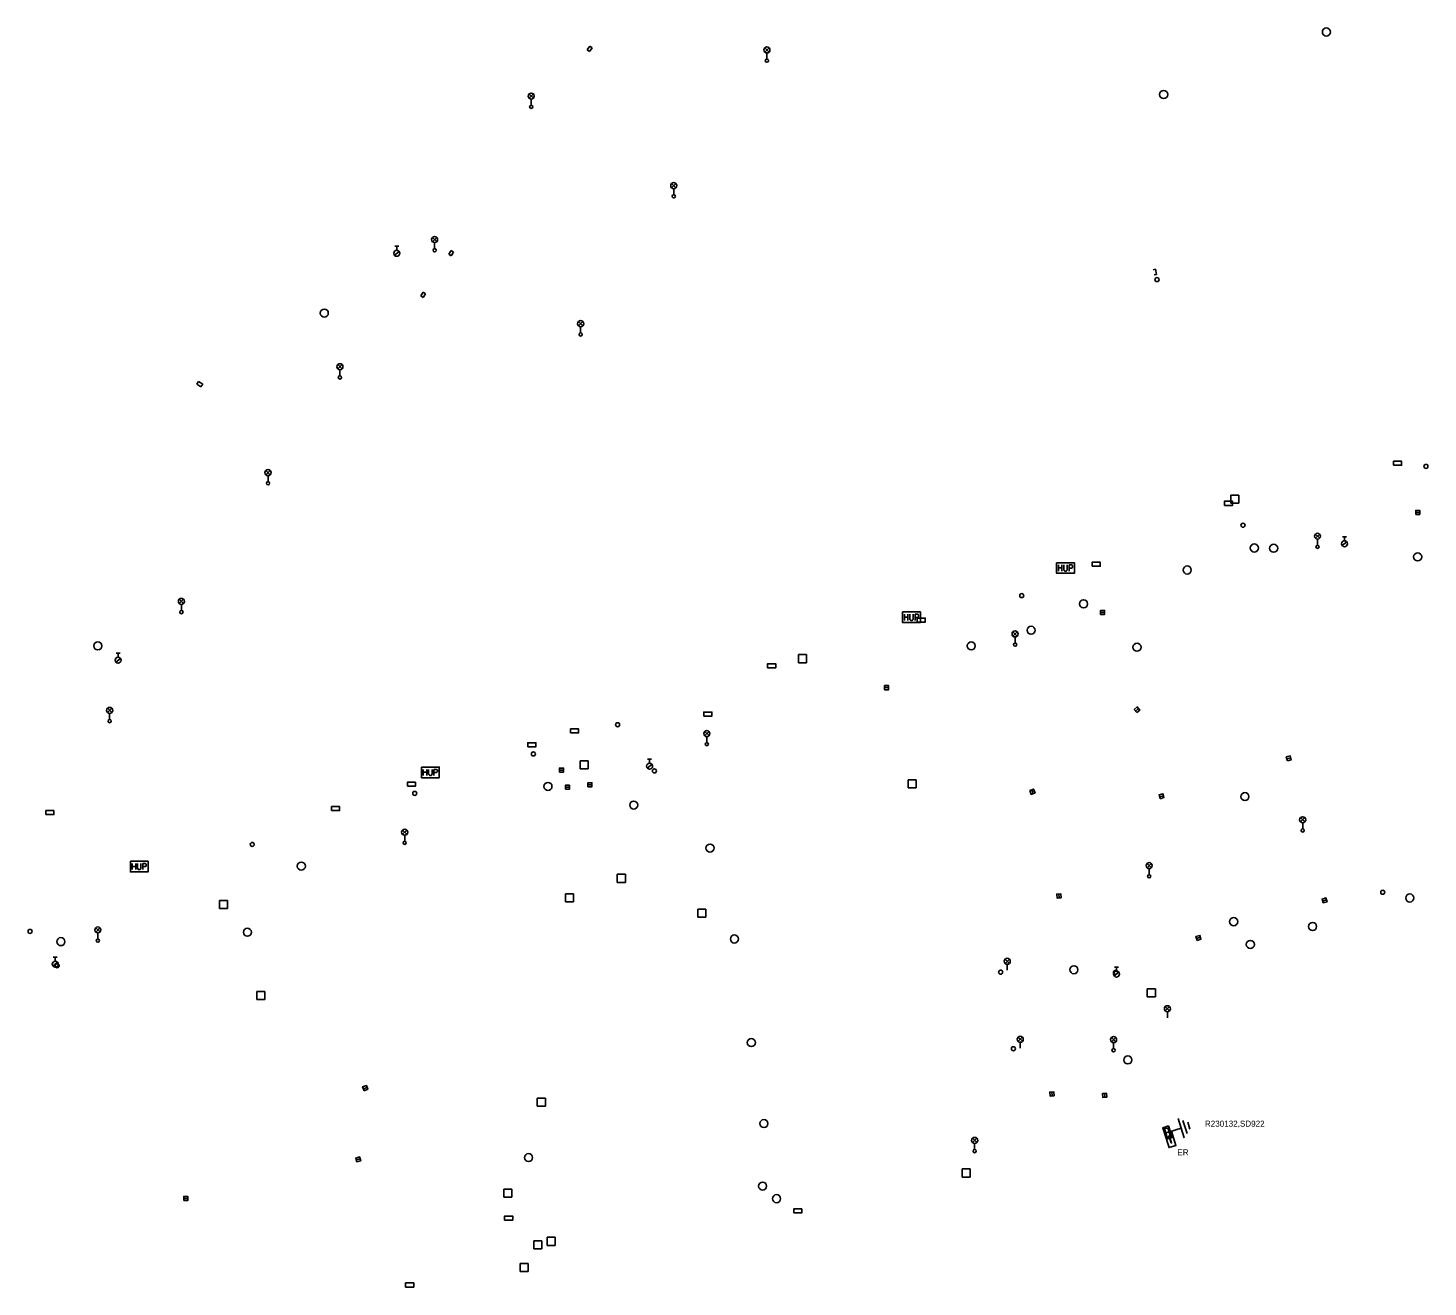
# Model space of a CAD drawing. Extents: x -584388 to -581645, y -1210859 to -1208922.
# Drawn here: x -583193 to -583019.2, y -1210722.4 to -1210566.1 of the extents above; entities that cross this region are included whole.
import ezdxf

# ---------------------------------------------------------------- set-up
doc = ezdxf.new("R2010")
doc.units = 0
for name, color, linetype in [('CIZÍ_NADZEM', 7, 'Continuous'), ('CIZÍ_PODZEM', 7, 'Continuous'), ('ELE_EON', 7, 'Continuous'), ('ELE_EON_POPIS', 7, 'Continuous')]:
    doc.layers.add(name, color=color, linetype=linetype)

msp = doc.modelspace()

# ---------------------------------------------------------------- linework, layer by layer
at = {"layer": 'CIZÍ_NADZEM'}
for p, q in [((-583101.55, -1210569.09), (-583101.03, -1210568.56)), ((-583101.02, -1210569.08), (-583101.55, -1210568.56)), ((-583101.29, -1210569.2), (-583101.29, -1210569.95)), ((-583130.82, -1210574.82), (-583130.3, -1210574.29)), ((-583130.29, -1210574.81), (-583130.82, -1210574.29)), ((-583130.56, -1210574.93), (-583130.56, -1210575.68)), ((-583113.12, -1210585.93), (-583112.6, -1210585.4)), ((-583112.59, -1210585.93), (-583113.12, -1210585.4)), ((-583112.86, -1210586.04), (-583112.86, -1210586.79)), ((-583142.81, -1210592.63), (-583142.29, -1210592.1)), ((-583142.28, -1210592.62), (-583142.81, -1210592.1)), ((-583147.54, -1210594.3), (-583146.95, -1210593.84)), ((-583147.5, -1210593.2), (-583147, -1210593.2)), ((-583147.25, -1210593.7), (-583147.25, -1210593.2)), ((-583142.55, -1210592.74), (-583142.55, -1210593.49)), ((-583124.68, -1210603.08), (-583124.16, -1210602.55)), ((-583124.15, -1210603.07), (-583124.68, -1210602.55)), ((-583124.42, -1210603.19), (-583124.42, -1210603.94)), ((-583154.57, -1210608.42), (-583154.05, -1210607.89)), ((-583154.04, -1210608.42), (-583154.57, -1210607.89)), ((-583154.31, -1210608.53), (-583154.31, -1210609.28)), ((-583163.5, -1210621.56), (-583162.98, -1210621.03)), ((-583162.97, -1210621.56), (-583163.5, -1210621.03)), ((-583163.24, -1210621.67), (-583163.24, -1210622.42)), ((-583042.71, -1210624.1), (-583043.71, -1210624.1)), ((-583043.71, -1210624.1), (-583043.71, -1210625.1)), ((-583043.71, -1210625.1), (-583042.71, -1210625.1)), ((-583042.71, -1210625.1), (-583042.71, -1210624.1)), ((-583020.74, -1210626.25), (-583020.24, -1210626.25)), ((-583033.19, -1210629.46), (-583032.67, -1210628.93)), ((-583032.66, -1210629.46), (-583033.19, -1210628.93)), ((-583032.93, -1210629.57), (-583032.93, -1210630.32)), ((-583029.87, -1210630.37), (-583029.28, -1210629.91)), ((-583029.83, -1210629.27), (-583029.33, -1210629.27)), ((-583029.58, -1210629.77), (-583029.58, -1210629.27)), ((-583174.25, -1210637.57), (-583173.73, -1210637.04)), ((-583173.72, -1210637.56), (-583174.25, -1210637.04)), ((-583173.99, -1210637.68), (-583173.99, -1210638.43)), ((-583059.86, -1210638.66), (-583059.36, -1210638.66)), ((-583070.74, -1210641.61), (-583070.22, -1210641.08)), ((-583070.21, -1210641.6), (-583070.74, -1210641.08)), ((-583070.48, -1210641.72), (-583070.48, -1210642.47)), ((-583182.1, -1210643.73), (-583181.6, -1210643.73)), ((-583181.85, -1210644.23), (-583181.85, -1210643.73)), ((-583096.39, -1210643.91), (-583097.39, -1210643.91)), ((-583097.39, -1210643.91), (-583097.39, -1210644.91)), ((-583096.39, -1210644.91), (-583096.39, -1210643.91)), ((-583182.14, -1210644.83), (-583181.55, -1210644.37)), ((-583097.39, -1210644.91), (-583096.39, -1210644.91)), ((-583086.69, -1210648.01), (-583086.19, -1210648.01)), ((-583183.16, -1210651.1), (-583182.64, -1210650.57)), ((-583182.63, -1210651.09), (-583183.16, -1210650.57)), ((-583055.53, -1210650.92), (-583055.15, -1210650.6)), ((-583182.9, -1210651.21), (-583182.9, -1210651.96)), ((-583109.01, -1210653.97), (-583108.49, -1210653.44)), ((-583108.48, -1210653.97), (-583109.01, -1210653.44)), ((-583108.75, -1210654.08), (-583108.75, -1210654.83)), ((-583123.5, -1210657.1), (-583124.5, -1210657.1)), ((-583124.5, -1210657.1), (-583124.5, -1210658.1)), ((-583124.5, -1210658.1), (-583123.5, -1210658.1)), ((-583123.5, -1210658.1), (-583123.5, -1210657.1)), ((-583116.15, -1210657.99), (-583115.56, -1210657.53)), ((-583116.11, -1210656.89), (-583115.61, -1210656.89)), ((-583115.86, -1210657.39), (-583115.86, -1210656.89)), ((-583036.73, -1210656.86), (-583036.25, -1210656.72)), ((-583127.05, -1210658.24), (-583126.55, -1210658.24)), ((-583082.76, -1210659.47), (-583083.76, -1210659.47)), ((-583083.76, -1210659.47), (-583083.76, -1210660.47)), ((-583082.76, -1210660.47), (-583082.76, -1210659.47)), ((-583126.32, -1210660.38), (-583125.82, -1210660.38)), ((-583123.52, -1210660.07), (-583123.02, -1210660.07)), ((-583083.76, -1210660.47), (-583082.76, -1210660.47)), ((-583068.42, -1210660.7), (-583068.24, -1210661.16)), ((-583052.54, -1210661.57), (-583052.06, -1210661.43)), ((-583035.03, -1210664.68), (-583034.51, -1210664.15)), ((-583034.5, -1210664.68), (-583035.03, -1210664.15)), ((-583034.77, -1210664.79), (-583034.77, -1210665.54)), ((-583146.53, -1210666.22), (-583146.01, -1210665.69)), ((-583146, -1210666.22), (-583146.53, -1210665.69)), ((-583146.27, -1210666.33), (-583146.27, -1210667.08)), ((-583054.09, -1210670.38), (-583053.57, -1210669.85)), ((-583053.56, -1210670.38), (-583054.09, -1210669.85)), ((-583118.87, -1210671.19), (-583119.87, -1210671.19)), ((-583119.87, -1210671.19), (-583119.87, -1210672.19)), ((-583118.87, -1210672.19), (-583118.87, -1210671.19)), ((-583053.83, -1210670.49), (-583053.83, -1210671.24)), ((-583125.29, -1210673.62), (-583126.29, -1210673.62)), ((-583126.29, -1210673.62), (-583126.29, -1210674.62)), ((-583125.29, -1210674.62), (-583125.29, -1210673.62)), ((-583119.87, -1210672.19), (-583118.87, -1210672.19)), ((-583065.02, -1210674.13), (-583065.06, -1210673.63)), ((-583168.28, -1210674.44), (-583169.28, -1210674.44)), ((-583169.28, -1210674.44), (-583169.28, -1210675.44)), ((-583169.28, -1210675.44), (-583168.28, -1210675.44)), ((-583168.28, -1210675.44), (-583168.28, -1210674.44)), ((-583126.29, -1210674.62), (-583125.29, -1210674.62)), ((-583108.89, -1210675.5), (-583109.89, -1210675.5)), ((-583109.89, -1210675.5), (-583109.89, -1210676.5)), ((-583108.89, -1210676.5), (-583108.89, -1210675.5)), ((-583032.29, -1210674.51), (-583031.81, -1210674.37)), ((-583109.89, -1210676.5), (-583108.89, -1210676.5)), ((-583184.63, -1210678.36), (-583184.11, -1210677.83)), ((-583184.1, -1210678.35), (-583184.63, -1210677.83)), ((-583184.37, -1210678.47), (-583184.37, -1210679.22)), ((-583047.95, -1210679.15), (-583047.47, -1210679.01)), ((-583189.95, -1210682.58), (-583189.36, -1210682.12)), ((-583189.91, -1210681.48), (-583189.41, -1210681.48)), ((-583189.66, -1210681.98), (-583189.66, -1210681.48)), ((-583071.71, -1210682.25), (-583071.19, -1210681.72)), ((-583071.18, -1210682.25), (-583071.71, -1210681.72)), ((-583071.45, -1210683.11), (-583071.45, -1210682.36)), ((-583058.18, -1210683.81), (-583057.59, -1210683.35)), ((-583058.14, -1210682.71), (-583057.64, -1210682.71)), ((-583057.89, -1210683.21), (-583057.89, -1210682.71)), ((-583163.63, -1210685.73), (-583164.63, -1210685.73)), ((-583164.63, -1210685.73), (-583164.63, -1210686.73)), ((-583163.63, -1210686.73), (-583163.63, -1210685.73)), ((-583053.06, -1210685.41), (-583054.06, -1210685.41)), ((-583054.06, -1210685.41), (-583054.06, -1210686.41)), ((-583053.06, -1210686.41), (-583053.06, -1210685.41)), ((-583164.63, -1210686.73), (-583163.63, -1210686.73)), ((-583054.06, -1210686.41), (-583053.06, -1210686.41)), ((-583051.83, -1210688.14), (-583051.31, -1210687.61)), ((-583051.3, -1210688.14), (-583051.83, -1210687.61)), ((-583051.57, -1210689), (-583051.57, -1210688.25)), ((-583070.1, -1210691.93), (-583069.58, -1210691.4)), ((-583069.57, -1210691.93), (-583070.1, -1210691.4)), ((-583069.84, -1210692.79), (-583069.84, -1210692.04)), ((-583058.51, -1210691.98), (-583057.99, -1210691.45)), ((-583057.98, -1210691.98), (-583058.51, -1210691.45)), ((-583058.25, -1210692.09), (-583058.25, -1210692.84)), ((-583151.4, -1210697.83), (-583150.94, -1210697.65)), ((-583128.8, -1210698.99), (-583129.8, -1210698.99)), ((-583129.8, -1210698.99), (-583129.8, -1210699.99)), ((-583128.8, -1210699.99), (-583128.8, -1210698.99)), ((-583065.88, -1210698.72), (-583065.92, -1210698.22)), ((-583059.39, -1210698.37), (-583059.35, -1210698.87)), ((-583129.8, -1210699.99), (-583128.8, -1210699.99)), ((-583075.76, -1210704.5), (-583075.24, -1210703.97)), ((-583075.23, -1210704.5), (-583075.76, -1210703.97)), ((-583075.5, -1210704.61), (-583075.5, -1210705.36)), ((-583152.27, -1210706.66), (-583151.79, -1210706.52)), ((-583076.04, -1210707.78), (-583077.04, -1210707.78)), ((-583077.04, -1210707.78), (-583077.04, -1210708.78)), ((-583076.04, -1210708.78), (-583076.04, -1210707.78)), ((-583132.97, -1210710.27), (-583133.97, -1210710.27)), ((-583133.97, -1210710.27), (-583133.97, -1210711.27)), ((-583132.97, -1210711.27), (-583132.97, -1210710.27)), ((-583077.04, -1210708.78), (-583076.04, -1210708.78)), ((-583173.7, -1210711.45), (-583173.2, -1210711.45)), ((-583133.97, -1210711.27), (-583132.97, -1210711.27)), ((-583129.25, -1210716.72), (-583130.25, -1210716.72)), ((-583130.25, -1210716.72), (-583130.25, -1210717.72)), ((-583129.25, -1210717.72), (-583129.25, -1210716.72)), ((-583127.58, -1210716.27), (-583128.58, -1210716.27)), ((-583128.58, -1210716.27), (-583128.58, -1210717.27)), ((-583127.58, -1210717.27), (-583127.58, -1210716.27)), ((-583130.25, -1210717.72), (-583129.25, -1210717.72)), ((-583128.58, -1210717.27), (-583127.58, -1210717.27)), ((-583130.94, -1210719.51), (-583131.94, -1210719.51)), ((-583131.94, -1210719.51), (-583131.94, -1210720.51)), ((-583131.94, -1210720.51), (-583130.94, -1210720.51)), ((-583130.94, -1210720.51), (-583130.94, -1210719.51))]:
    msp.add_line(p, q, dxfattribs=at)
for points in [[(-583053.35, -1210596.12), (-583053.05, -1210596.05), (-583052.91, -1210596.7)], [(-583053.2, -1210596.76), (-583052.91, -1210596.7)], [(-583065.32, -1210632.49), (-583063.12, -1210632.49), (-583063.12, -1210633.81), (-583065.32, -1210633.81), (-583065.32, -1210632.49)], [(-583065.1, -1210632.77), (-583065.1, -1210633.54)], [(-583065.1, -1210633.13), (-583064.66, -1210633.13)], [(-583064.66, -1210633.54), (-583064.66, -1210632.77)], [(-583064.44, -1210632.77), (-583064.44, -1210633.32), (-583064.41, -1210633.43), (-583064.34, -1210633.5), (-583064.25, -1210633.54), (-583064.18, -1210633.54), (-583064.09, -1210633.5), (-583064.03, -1210633.43), (-583064, -1210633.32), (-583064, -1210632.77)], [(-583063.78, -1210632.77), (-583063.49, -1210632.77), (-583063.4, -1210632.8), (-583063.37, -1210632.84), (-583063.34, -1210632.91), (-583063.34, -1210633.02), (-583063.37, -1210633.09), (-583063.4, -1210633.13), (-583063.49, -1210633.17), (-583063.78, -1210633.17)], [(-583063.78, -1210633.54), (-583063.78, -1210632.77)], [(-583084.44, -1210638.6), (-583082.24, -1210638.6), (-583082.24, -1210639.92), (-583084.44, -1210639.92), (-583084.44, -1210638.6)], [(-583084.22, -1210638.88), (-583084.22, -1210639.65)], [(-583083.78, -1210639.65), (-583083.78, -1210638.88)], [(-583083.56, -1210638.88), (-583083.56, -1210639.43), (-583083.53, -1210639.53), (-583083.46, -1210639.61), (-583083.37, -1210639.65), (-583083.3, -1210639.65), (-583083.21, -1210639.61), (-583083.15, -1210639.53), (-583083.12, -1210639.43), (-583083.12, -1210638.88)], [(-583082.9, -1210638.88), (-583082.61, -1210638.88), (-583082.52, -1210638.91), (-583082.49, -1210638.95), (-583082.46, -1210639.02), (-583082.46, -1210639.13), (-583082.49, -1210639.2), (-583082.52, -1210639.24), (-583082.61, -1210639.28), (-583082.9, -1210639.28)], [(-583082.9, -1210639.65), (-583082.9, -1210638.88)], [(-583084.22, -1210639.24), (-583083.78, -1210639.24)], [(-583144.18, -1210657.88), (-583141.98, -1210657.88), (-583141.98, -1210659.2), (-583144.18, -1210659.2), (-583144.18, -1210657.88)], [(-583143.96, -1210658.16), (-583143.96, -1210658.93)], [(-583143.52, -1210658.93), (-583143.52, -1210658.16)], [(-583143.3, -1210658.16), (-583143.3, -1210658.71), (-583143.27, -1210658.81), (-583143.2, -1210658.89), (-583143.11, -1210658.93), (-583143.04, -1210658.93), (-583142.95, -1210658.89), (-583142.89, -1210658.81), (-583142.86, -1210658.71), (-583142.86, -1210658.16)], [(-583142.64, -1210658.16), (-583142.35, -1210658.16), (-583142.26, -1210658.19), (-583142.23, -1210658.23), (-583142.2, -1210658.3), (-583142.2, -1210658.41), (-583142.23, -1210658.48), (-583142.26, -1210658.52), (-583142.35, -1210658.55), (-583142.64, -1210658.55)], [(-583142.64, -1210658.93), (-583142.64, -1210658.16)], [(-583143.96, -1210658.52), (-583143.52, -1210658.52)], [(-583180.33, -1210669.57), (-583178.13, -1210669.57), (-583178.13, -1210670.89), (-583180.33, -1210670.89), (-583180.33, -1210669.57)], [(-583180.11, -1210669.84), (-583180.11, -1210670.61)], [(-583180.11, -1210670.21), (-583179.67, -1210670.21)], [(-583179.67, -1210670.61), (-583179.67, -1210669.84)], [(-583179.45, -1210669.84), (-583179.45, -1210670.4), (-583179.42, -1210670.51), (-583179.35, -1210670.58), (-583179.26, -1210670.61), (-583179.2, -1210670.61), (-583179.1, -1210670.58), (-583179.04, -1210670.51), (-583179.01, -1210670.4), (-583179.01, -1210669.84)], [(-583178.79, -1210669.84), (-583178.5, -1210669.84), (-583178.41, -1210669.88), (-583178.38, -1210669.92), (-583178.35, -1210669.99), (-583178.35, -1210670.1), (-583178.38, -1210670.17), (-583178.41, -1210670.21), (-583178.5, -1210670.24), (-583178.79, -1210670.24)], [(-583178.79, -1210670.61), (-583178.79, -1210669.84)]]:
    msp.add_lwpolyline(points, dxfattribs=at)
for points in [[(-583023.48, -1210620.39), (-583022.48, -1210620.39), (-583022.48, -1210619.89), (-583023.48, -1210619.89)], [(-583044.48, -1210625.37), (-583043.48, -1210625.37), (-583043.48, -1210624.87), (-583044.48, -1210624.87)], [(-583020.74, -1210626.5), (-583020.24, -1210626.5), (-583020.24, -1210626), (-583020.74, -1210626)], [(-583060.91, -1210632.94), (-583059.91, -1210632.94), (-583059.91, -1210632.44), (-583060.91, -1210632.44)], [(-583059.86, -1210638.91), (-583059.36, -1210638.91), (-583059.36, -1210638.41), (-583059.86, -1210638.41)], [(-583082.64, -1210639.87), (-583081.64, -1210639.87), (-583081.64, -1210639.37), (-583082.64, -1210639.37)], [(-583101.2, -1210645.54), (-583100.2, -1210645.54), (-583100.2, -1210645.04), (-583101.2, -1210645.04)], [(-583086.69, -1210648.26), (-583086.19, -1210648.26), (-583086.19, -1210647.76), (-583086.69, -1210647.76)], [(-583109.13, -1210651.54), (-583108.13, -1210651.54), (-583108.13, -1210651.04), (-583109.13, -1210651.04)], [(-583055.37, -1210651.11), (-583054.99, -1210650.79), (-583055.31, -1210650.41), (-583055.69, -1210650.73)], [(-583125.68, -1210653.64), (-583124.68, -1210653.64), (-583124.68, -1210653.14), (-583125.68, -1210653.14)], [(-583130.98, -1210655.35), (-583129.98, -1210655.35), (-583129.98, -1210654.85), (-583130.98, -1210654.85)], [(-583127.05, -1210658.49), (-583126.55, -1210658.49), (-583126.55, -1210657.99), (-583127.05, -1210657.99)], [(-583036.66, -1210657.1), (-583036.18, -1210656.96), (-583036.32, -1210656.48), (-583036.8, -1210656.62)], [(-583145.94, -1210660.25), (-583144.94, -1210660.25), (-583144.94, -1210659.75), (-583145.94, -1210659.75)], [(-583123.52, -1210660.32), (-583123.02, -1210660.32), (-583123.02, -1210659.82), (-583123.52, -1210659.82)], [(-583126.32, -1210660.63), (-583125.82, -1210660.63), (-583125.82, -1210660.13), (-583126.32, -1210660.13)], [(-583068.66, -1210660.79), (-583068.47, -1210661.26), (-583068, -1210661.07), (-583068.19, -1210660.6)], [(-583052.47, -1210661.81), (-583051.99, -1210661.67), (-583052.13, -1210661.19), (-583052.61, -1210661.33)], [(-583190.82, -1210663.78), (-583189.82, -1210663.78), (-583189.82, -1210663.28), (-583190.82, -1210663.28)], [(-583155.35, -1210663.28), (-583154.35, -1210663.28), (-583154.35, -1210662.78), (-583155.35, -1210662.78)], [(-583064.77, -1210674.11), (-583064.8, -1210673.61), (-583065.31, -1210673.65), (-583065.27, -1210674.14)], [(-583032.22, -1210674.75), (-583031.74, -1210674.61), (-583031.88, -1210674.13), (-583032.36, -1210674.27)], [(-583047.88, -1210679.39), (-583047.4, -1210679.25), (-583047.54, -1210678.77), (-583048.02, -1210678.91)], [(-583151.32, -1210698.06), (-583150.85, -1210697.89), (-583151.02, -1210697.42), (-583151.49, -1210697.59)], [(-583065.63, -1210698.7), (-583065.67, -1210698.2), (-583066.17, -1210698.24), (-583066.13, -1210698.74)], [(-583059.64, -1210698.39), (-583059.6, -1210698.89), (-583059.1, -1210698.85), (-583059.14, -1210698.35)], [(-583152.2, -1210706.9), (-583151.72, -1210706.76), (-583151.86, -1210706.28), (-583152.34, -1210706.42)], [(-583173.7, -1210711.7), (-583173.2, -1210711.7), (-583173.2, -1210711.2), (-583173.7, -1210711.2)], [(-583133.86, -1210714.13), (-583132.86, -1210714.13), (-583132.86, -1210713.63), (-583133.86, -1210713.63)], [(-583097.97, -1210713.24), (-583096.97, -1210713.24), (-583096.97, -1210712.74), (-583097.97, -1210712.74)], [(-583146.15, -1210722.44), (-583145.15, -1210722.44), (-583145.15, -1210721.94), (-583146.15, -1210721.94)]]:
    msp.add_lwpolyline(points, close=True, dxfattribs=at)
for centre, radius in [((-583031.83, -1210566.59), 0.5), ((-583101.29, -1210568.82), 0.375), ((-583101.29, -1210570.15), 0.2), ((-583130.56, -1210574.55), 0.375), ((-583052.03, -1210574.35), 0.5), ((-583130.56, -1210575.88), 0.2), ((-583112.86, -1210585.67), 0.375), ((-583112.86, -1210586.99), 0.2), ((-583142.55, -1210592.36), 0.375), ((-583147.25, -1210594.07), 0.375), ((-583142.55, -1210593.69), 0.2), ((-583052.86, -1210597.34), 0.25), ((-583156.25, -1210601.5), 0.5), ((-583124.42, -1210602.81), 0.375), ((-583124.42, -1210604.14), 0.2), ((-583154.31, -1210608.16), 0.375), ((-583154.31, -1210609.48), 0.2), ((-583163.24, -1210621.3), 0.375), ((-583019.46, -1210620.53), 0.25), ((-583163.24, -1210622.62), 0.2), ((-583042.18, -1210627.84), 0.25), ((-583040.77, -1210630.67), 0.5), ((-583038.37, -1210630.7), 0.5), ((-583032.93, -1210629.2), 0.375), ((-583032.93, -1210630.52), 0.2), ((-583029.58, -1210630.14), 0.375), ((-583020.49, -1210631.77), 0.5), ((-583049.11, -1210633.4), 0.5), ((-583173.99, -1210637.3), 0.375), ((-583069.66, -1210636.58), 0.25), ((-583061.98, -1210637.6), 0.5), ((-583173.99, -1210638.63), 0.2), ((-583068.49, -1210640.88), 0.5), ((-583184.37, -1210642.82), 0.5), ((-583075.92, -1210642.82), 0.5), ((-583070.48, -1210641.34), 0.375), ((-583070.48, -1210642.67), 0.2), ((-583055.34, -1210642.99), 0.5), ((-583181.85, -1210644.6), 0.375), ((-583182.9, -1210650.83), 0.375), ((-583182.9, -1210652.16), 0.2), ((-583119.83, -1210652.61), 0.25), ((-583108.75, -1210653.71), 0.375), ((-583130.29, -1210656.24), 0.25), ((-583108.75, -1210655.03), 0.2), ((-583115.86, -1210657.76), 0.375), ((-583115.26, -1210658.35), 0.25), ((-583128.48, -1210660.28), 0.5), ((-583145.02, -1210661.14), 0.25), ((-583041.94, -1210661.54), 0.5), ((-583117.83, -1210662.59), 0.5), ((-583034.77, -1210664.42), 0.375), ((-583146.27, -1210665.96), 0.375), ((-583034.77, -1210665.74), 0.2), ((-583165.2, -1210667.48), 0.25), ((-583146.27, -1210667.28), 0.2), ((-583108.36, -1210667.93), 0.5), ((-583159.1, -1210670.17), 0.5), ((-583053.83, -1210670.11), 0.375), ((-583053.83, -1210671.44), 0.2), ((-583024.83, -1210673.42), 0.25), ((-583021.47, -1210674.13), 0.5), ((-583043.34, -1210677.07), 0.5), ((-583033.54, -1210677.67), 0.5), ((-583192.79, -1210678.28), 0.25), ((-583184.37, -1210678.09), 0.375), ((-583165.8, -1210678.38), 0.5), ((-583105.33, -1210679.22), 0.5), ((-583188.96, -1210679.55), 0.5), ((-583184.37, -1210679.42), 0.2), ((-583041.27, -1210679.9), 0.5), ((-583189.66, -1210682.35), 0.375), ((-583189.42, -1210682.54), 0.25), ((-583071.45, -1210681.99), 0.375), ((-583072.27, -1210683.34), 0.25), ((-583063.18, -1210683.04), 0.5), ((-583057.89, -1210683.58), 0.375), ((-583058.01, -1210683.36), 0.25), ((-583051.57, -1210687.88), 0.375), ((-583103.23, -1210692.09), 0.5), ((-583070.69, -1210692.85), 0.25), ((-583069.84, -1210691.67), 0.375), ((-583058.25, -1210691.72), 0.375), ((-583058.25, -1210693.04), 0.2), ((-583056.48, -1210694.24), 0.5), ((-583101.67, -1210702.14), 0.5), ((-583075.5, -1210704.24), 0.375), ((-583130.89, -1210706.37), 0.5), ((-583075.5, -1210705.56), 0.2), ((-583101.83, -1210709.91), 0.5), ((-583100.1, -1210711.47), 0.5)]:
    msp.add_circle(centre, radius, dxfattribs=at)
at = {"layer": 'CIZÍ_PODZEM'}
for points in [[(-583123.6, -1210568.8), (-583123.3, -1210568.35)], [(-583123.6, -1210568.8), (-583123.31, -1210569)], [(-583123.01, -1210568.54), (-583123.31, -1210569)], [(-583123.01, -1210568.54), (-583123.3, -1210568.35)], [(-583140.79, -1210594.17), (-583140.48, -1210593.71)], [(-583140.19, -1210593.91), (-583140.48, -1210593.71)], [(-583140.79, -1210594.17), (-583140.5, -1210594.37)], [(-583140.19, -1210593.91), (-583140.5, -1210594.37)], [(-583144.28, -1210599.36), (-583143.97, -1210598.9)], [(-583143.68, -1210599.1), (-583143.97, -1210598.9)], [(-583144.28, -1210599.36), (-583143.99, -1210599.56)], [(-583143.68, -1210599.1), (-583143.99, -1210599.56)], [(-583172.07, -1210610.31), (-583171.85, -1210609.98)], [(-583172.07, -1210610.31), (-583171.57, -1210610.65)], [(-583171.35, -1210610.32), (-583171.85, -1210609.98)], [(-583171.35, -1210610.32), (-583171.57, -1210610.65)]]:
    msp.add_lwpolyline(points, dxfattribs=at)
at = {"layer": 'ELE_EON'}
for p, q in [((-583049.48, -1210703.91), (-583050.25, -1210701.53)), ((-583049.86, -1210702.72), (-583051.29, -1210703.18)), ((-583049.13, -1210703.38), (-583049.65, -1210701.76)), ((-583048.77, -1210702.84), (-583049.05, -1210701.99))]:
    msp.add_line(p, q, dxfattribs=at)
for points in [[(-583051.43, -1210702.44), (-583050.97, -1210703.86), (-583051.68, -1210704.09), (-583052.14, -1210702.67)], [(-583051.51, -1210702.67), (-583051.17, -1210703.72), (-583051.6, -1210703.86), (-583051.94, -1210702.81)], [(-583051.92, -1210703.34), (-583051.36, -1210705.12), (-583050.5, -1210704.86), (-583051.06, -1210703.07)], [(-583051.37, -1210703.65), (-583051.09, -1210704.55), (-583051.05, -1210704.54), (-583051.33, -1210703.64)]]:
    msp.add_lwpolyline(points, close=True, dxfattribs=at)

# ---------------------------------------------------------------- texts
at = {"layer": 'ELE_EON_POPIS'}
for s, p in [('R230132,SD922', (-583046.91, -1210702.53)), ('ER', (-583050.33, -1210706.09))]:
    msp.add_text(s, height=0.75, dxfattribs=at).set_placement(p)

doc.saveas('drawing.dxf')
